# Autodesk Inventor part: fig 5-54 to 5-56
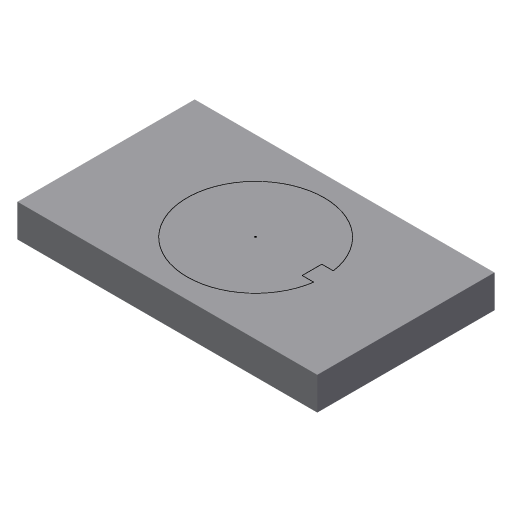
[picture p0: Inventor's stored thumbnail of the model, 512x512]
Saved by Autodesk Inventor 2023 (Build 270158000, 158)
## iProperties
Created: 2005-12
Part Number: fig 5-54 to 5-56
Document SubType Name: Modeling
Designer: CADCIM
Density: 1 g/cm^3
Material: Generic
Appearance: Default
Author: CADCIM
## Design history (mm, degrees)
sketch "Sketch1"
  geometry: L1 (-47.674, -20.831)-(44.057, -20.831); L2 (44.057, -20.831)-(44.057, 33.398); L3 (44.057, 33.398)-(-47.674, 33.398); L4 (-47.674, 33.398)-(-47.674, -20.831)
  constraints: 8 end point, 2 parallel, 1 horizontal, 1 perpendicular
extrude "Extrusion1" new body sketch "Sketch1" distance "d0" = 10; taper "d1" = 0 deg
sketch "Sketch2"
  geometry: L1 (15.359, 9.199)-(18.885, 9.199); L2 (18.885, 3.199)-(15.359, 3.199); L3 (15.359, 3.199)-(15.359, 9.199); A1 r 20.978 centre (-1.877, 6.199) between (18.885, 9.199) and (18.885, 3.199)
  constraints: 6 end point, 2 parallel, 2 point on circle, 1 centre point, 1 horizontal, 1 vertical
body "Solid1"
